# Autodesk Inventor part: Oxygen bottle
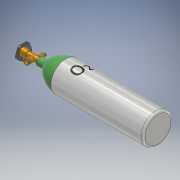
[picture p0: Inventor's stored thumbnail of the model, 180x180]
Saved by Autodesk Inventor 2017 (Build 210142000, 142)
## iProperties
Created: 2020-03
Part Number: Oxygen bottle
Material: Generic
Document SubType Name: Modeling
Designer: user
Density: 1 g/cm^3
Appearance: Default
Author: user
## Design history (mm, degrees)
sketch "Sketch1"
  geometry: L1 (0, 0)-(0, 65); L2 (10, 75)-(461.493, 75); L3 (560, 20)-(560, 0); L4 (560, 0)-(0, 0); A1 r 146.454 centre (444.859, -70.506) between (560, 20) and (461.493, 75); A2 r 10 centre (10, 65) between (10, 75) and (0, 65); 1 further point
  constraints: 8 end point, 4 point on circle, 3 perpendicular, 2 centre point, 2 point on line, 2 tangent, 1 vertical
  dimensions: "d0" = 75 distance of L1.start point (0, 75); "d2" = 560 distance from line of point (0, 75) L3; "d6" = 10 radius of A2; "d8" = 20 distance of L3.start L3.end
revolve "Revolution1" sketch "Sketch1" stored, may be unused: angle "d7" = 90 deg
sketch "Sketch2"
  geometry: C1 r 20 at (0, 0); C2 r 20 at (0, 0) reference; 1 further point
  constraints: 1 centre point, 1 coincident, 1 concentric
extrude "Extrusion1" join sketch "Sketch2" distance "d9" = 30; taper "d10" = 0 deg
workplane "Work Plane1"
sketch "Sketch3"
  geometry: C1 r 16 at (0, 0); 1 further point
  constraints: 1 centre point, 1 coincident
  dimensions: "d12" = 32 diameter of C1
loft "Loft1" sketch "Sketch3" dims "d13" = 10, "d14" = 90 deg, "d15" = 0, "d16" = 90 deg
  node "Edges1"
sketch "Sketch4"
  geometry: C1 r 14 at (0, 0); 1 further point
  constraints: 1 centre point, 1 coincident
  dimensions: "d17" = 28 diameter of C1
extrude "Extrusion2" join sketch "Sketch4" distance "d18" = 55; taper "d19" = 0 deg
sketch "Sketch5"
  geometry: C1 r 11.646 at (607.574, 0); 1 further point
  constraints: 1 centre point
extrude "Extrusion3" join sketch "Sketch5" distance "d20" = 30; taper "d21" = 0 deg
sketch "Sketch6"
  geometry: C1 r 12.412 at (620.618, 0); 1 further point
  constraints: 1 centre point
extrude "Extrusion4" join sketch "Sketch6" distance "d22" = 40; taper "d23" = 0 deg
sketch "Sketch7"
  geometry: C1 r 17.5 at (0, 0); 1 further point
  constraints: 1 centre point, 1 coincident
  dimensions: "d24" = 35 diameter of C1
extrude "Extrusion5" join sketch "Sketch7" distance "d25" = 20; taper "d26" = 0 deg
sketch "Sketch8"
  geometry: L1 (-35.907, 7.641)-(-18.363, 31.789); L2 (-3.829, 36.511)-(24.558, 27.288); L3 (33.541, 14.924)-(33.541, -14.924); L4 (24.558, -27.288)-(-3.829, -36.511); L5 (-18.363, -31.789)-(-35.907, -7.641); C1 r 14 at (0, 0) reference; A1 r 13 centre (-7.846, -24.147) between (-18.363, -31.789) and (-3.829, -36.511); A2 r 13 centre (20.541, -14.924) between (24.558, -27.288) and (33.541, -14.924); A3 r 13 centre (20.541, 14.924) between (33.541, 14.924) and (24.558, 27.288); A4 r 13 centre (-7.846, 24.147) between (-3.829, 36.511) and (-18.363, 31.789); A5 r 13 centre (-25.39, 0) between (-35.907, 7.641) and (-35.907, -7.641); 7 further points
  constraints: 10 end point, 10 point on circle, 10 point on line, 10 tangent, 5 centre point, 4 equal radius, 1 coincident, 11 other
  dimensions: "d27" = 75 distance from line of L3 point (-41.459, 0); "d28" = 13 radius of A1
extrude "Extrusion6" join sketch "Sketch8" distance "d29" = 12; taper "d30" = 0 deg
shell "Shell1" dims "d31" = 3
sketch "Sketch9"
  geometry: C1 r 14.5 at (0, 0) reference; C2 r 17.5 at (0, 0); 1 further point
  constraints: 1 centre point, 1 coincident
extrude "Extrusion7" join sketch "Sketch9" stored distance "d32" = 12; taper "d33" = 0 deg
fillet "Fillet1" dims "d34" = 3
sketch "Sketch10"
  geometry: C1 r 6.35 at (0, 0); 1 further point
  constraints: 1 centre point
  dimensions: "d35" = 12.7 diameter of C1
extrude "Extrusion8" join sketch "Sketch10" distance "d36" = 12; taper "d37" = 0 deg
fillet "Fillet2" dims "d38" = 1.5
thread "Thread1" dims "d39" = 7, "d40" = 0
sketch "Sketch11"
  geometry: C1 r 5.5 at (0, 0); 1 further point
  constraints: 1 centre point
  dimensions: "d41" = 11 diameter of C1
extrude "Extrusion9" cut sketch "Sketch11" distance "d42" = 12; taper "d43" = 0 deg
thread "Thread2" dims "d44" = 15, "d45" = 0
sketch "Sketch12"
  geometry: C1 r 10.281 at (0, 0); 1 further point
  constraints: 1 centre point
extrude "Extrusion10" cut sketch "Sketch12" distance "d46" = 40; taper "d47" = 0 deg
workplane "Work Plane2"
sketch "Sketch13"
  geometry: L1 (-412.375, -41.707)-(-412.375, 59.461); L2 (-412.375, 59.461)-(-303.078, 59.461); L3 (-303.078, 59.461)-(-303.078, -41.707); L4 (-303.078, -41.707)-(-412.375, -41.707); L5 (-388.391, 10.546)-(-388.391, 93.67); L6 (-388.391, 93.67)-(-293.969, 93.67); L7 (-293.969, 93.67)-(-293.969, 10.546); L8 (-293.969, 10.546)-(-388.391, 10.546); 1 further point
  constraints: 4 other
emboss "Emboss1" sketch "Sketch13" dims "d0" = 75, "d2" = 560, "d6" = 10, "d8" = 20, "d49" = 0.1, "d50" = 0
body "Solid1"
other parameters: "d11" = 4, "d48" = 75
